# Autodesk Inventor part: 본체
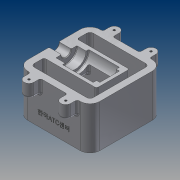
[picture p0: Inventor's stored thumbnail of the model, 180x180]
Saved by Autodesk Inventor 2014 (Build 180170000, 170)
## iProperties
Created: 2018-01
Part Number: 본체
Material: 알루미늄 6061
Document SubType Name: Modeling
Designer: user
Mass: 999.317 g
Surface Area: 835.945 cm^2
Volume: 368.752 cm^3
Density: 2.71 g/cm^3
Appearance: 알루미늄 - 평지
Author: user
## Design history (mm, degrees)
sketch "스케치2"
  geometry: L1 (-55, -55)-(55, -55); L2 (55, -55)-(55, 55); L3 (55, 55)-(-55, 55); L4 (-55, 55)-(-55, -55); L5 (-55, -55)-(55, 55); L6 (55, -55)-(-55, 55); L7 (-45, 45)-(45, 45); L8 (45, 45)-(45, -45); L9 (45, -45)-(-45, -45); L10 (-45, -45)-(-45, 45); L11 (-45, 45)-(45, -45); L12 (45, 45)-(-45, -45); 1 further point
  constraints: 24 end point, 4 midpoint, 4 parallel, 2 horizontal, 2 perpendicular
  dimensions: "d0" = 110 distance of L2.end L3.end; "d1" = 110 distance of L1.end L2.end; "d2" = 90 distance of L7.start L7.end; "d3" = 90 distance of L7.end L8.end
extrude "돌출1" new body sketch "스케치2" distance "d4" = 65; taper "d5" = 0 deg
fillet "모깎기1" dims "d6" = 15
fillet "모깎기2" dims "d7" = 5
sketch "스케치3"
  geometry: L1 (-55, 0)-(-55, 65) reference; L2 (-55, 65)-(35, 65); L3 (35, 65)-(35, 0); L4 (35, 0)-(-55, 0); L5 (-55, 0)-(-55, 65); L6 (40, 0)-(-40, 0) reference; L7 (55, 65)-(55, 0) reference; 2 further points
  constraints: 8 end point, 2 parallel, 1 horizontal, 1 horizontal alignment, 1 midpoint, 1 perpendicular
  dimensions: "d8" = 20 distance between parallel lines of L3 L7
extrude "돌출2" join sketch "스케치3" stored distance "d9" = 50; taper "d10" = 0 deg
sketch "스케치5"
  geometry: L1 (-55, 40)-(-55, -40) reference; L2 (-55, 0)-(35, 0); L3 (35, -25)-(35, 25) reference; L4 (-55, 0)-(-55, 7.5); L5 (-55, 7.5)-(-36, 7.5); L6 (-36, 7.5)-(-36, 16); L7 (-36, 16)-(-22, 16); L8 (-22, 16)-(-22, 20); L9 (-22, 20)-(25, 20); L10 (25, 20)-(25, 15); L11 (25, 15)-(30, 15); L12 (30, 15)-(30, 0); 1 further point
  constraints: 20 end point, 5 parallel, 4 perpendicular, 2 midpoint, 2 point on line
  dimensions: "d11" = 15 diameter of L5 L2; "d12" = 19 distance of L4.end L5.end; "d13" = 14 distance of L6.end L7.end; "d14" = 32 diameter of L7 L2; "d15" = 40 diameter of L9 L2; "d16" = 47 distance of L8.end L9.end; "d17" = 5 distance of L10.end L11.end; "d18" = 30 diameter of L11 L2
revolve "회전1" sketch "스케치5" stored, may be unused: angle "d19" = 90 deg
sketch "스케치6"
  geometry: L1 (25, 45)-(-22, 45) reference; L2 (35, 65)-(35, 0) reference; L3 (35, 0)-(-45, 0) reference; L4 (35, 30)-(-45, 8.564); L5 (-45, 8.564)-(-45, 0); L6 (-55, 0)-(-55, 65) reference; 1 further point
  constraints: 4 end point, 2 point on line, 1 perpendicular
  dimensions: "d20" = 30 distance of L2.end L4.start; "d21" = 105 deg angle of L4 L5; "d22" = 10 distance between parallel lines of L6 L5
extrude "돌출3" cut sketch "스케치6" stored distance "d23" = 50; taper "d24" = 0 deg
sketch "스케치7"
  geometry: L1 (35, 30)-(-45, 8.564) reference; L2 (20, 31.157)-(-55, 11.061); L3 (-55, 0)-(-55, 65) reference; L4 (-55, 29.061)-(-17, 39.243); L5 (-17, 39.243)-(-17, 51.224); L6 (-17, 51.224)-(20, 51.224); L7 (20, 51.224)-(20, 31.157); L8 (-22, 65)-(-22, 45) reference; 1 further point
  constraints: 10 end point, 4 parallel, 2 point on line, 1 perpendicular
  dimensions: "d25" = 5 distance between parallel lines of L2 L1; "d26" = 18 distance of L4.start L2.end; "d27" = 37 distance between parallel lines of L7 L5; "d28" = 5 distance between parallel lines of L8 L5
extrude "돌출4" cut sketch "스케치7" stored distance "d29" = 30; taper "d30" = 0 deg
fillet "모깎기3" dims "d31" = 1
chamfer "모따기1" distance "d32" = 1; stored, may be unused: second distance "d33" = 2, angle "d34" = 45 deg
fillet "모깎기4" dims "d35" = 3
sketch "스케치8"
  geometry: L1 (-55, 40)-(-55, 8.5) reference; L2 (40, 55)-(-40, 55) reference; L3 (-35.5, 65)-(-35.5, 55); L4 (-20.5, 65)-(-20.5, 55); L5 (20.5, 65)-(20.5, 55); L6 (35.5, 65)-(35.5, 55); A1 r 7.5 centre (-28, 65) between (-35.5, 65) and (-20.5, 65); A2 r 7.5 centre (28, 65) between (20.5, 65) and (35.5, 65); 1 further point
  constraints: 8 end point, 4 perpendicular, 4 point on circle, 4 point on line, 4 tangent, 2 centre point, 1 horizontal alignment
  dimensions: "d36" = 15 diameter of A1; "d38" = 10 distance from line of L2 A1.centre; "d39" = 15 diameter of A2; "d40" = 56 distance of A2.centre A1.centre; "d57" = 19.5 distance between parallel lines of L1 L3
extrude "돌출5" join sketch "스케치8" distance "d41" = 20; taper "d42" = 0 deg
sketch "스케치9"
  geometry: A1 r 7.5 centre (-28, 65) between (-20.5, 65) and (-35.5, 65) reference; A2 r 7.5 centre (28, 65) between (35.5, 65) and (20.5, 65) reference; 3 further points
  constraints: 2 coincident
hole "구멍1" sketch "스케치9" at (-28, 65), (28, 65) diameter "d43" = 3.242; stored, may be unused: countersink angle "d47" = 90 deg, drill point angle "d49" = 118 deg; dims "d44" = 9, "d45" = 4, "d46" = 2, "d48" = 11
fillet "모깎기5" dims "d50" = 3
fillet "모깎기6" dims "d51" = 3
sketch "스케치10"
  geometry: L1 (-15, 65)-(-15, 0) reference; 2 further points
  constraints: 1 other
  dimensions: "d52" = 55 distance from line of L1 point (40, 20); "d53" = 20 distance of point (40, 0) point (40, 20)
feature "엠보싱1" sketch "스케치10" dims "d0" = 110, "d1" = 110, "d54" = 0.5, "d55" = 0
fillet "모깎기7" dims "d56" = 3
chamfer "모따기2" distance "d58" = 1; stored, may be unused: second distance "d59" = 2, angle "d60" = 45 deg
node "솔리드1"
mirror "대칭1"
mirror "대칭2"
